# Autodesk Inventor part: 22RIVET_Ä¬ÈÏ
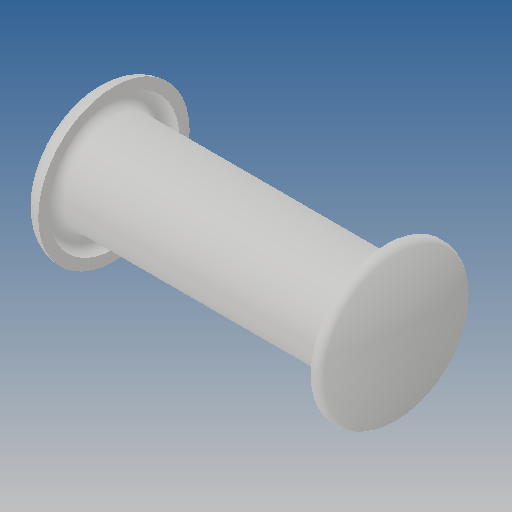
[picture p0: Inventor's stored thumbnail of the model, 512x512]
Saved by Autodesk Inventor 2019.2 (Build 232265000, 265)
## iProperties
Created: 2010-06
Part Number: 22RIVET_Ä¬ÈÏ
Material: Ogólny
Document SubType Name: Modeling
Designer: CADENGINEERING4
Density: 1 g/cm^3
Appearance: Domyślna
Author: CADENGINEERING4
Revision Number: ÈÎºÎ
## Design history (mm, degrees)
feature "NONE"
node "Bryła1"
